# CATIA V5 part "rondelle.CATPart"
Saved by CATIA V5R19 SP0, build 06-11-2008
Part number: rondelle
Bounding box of the stored display mesh (mm): x 0 to 2.876, y -10 to 10, z -9.511 to 9.511
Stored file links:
  I:\mediator\rondelle.CATPart
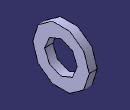
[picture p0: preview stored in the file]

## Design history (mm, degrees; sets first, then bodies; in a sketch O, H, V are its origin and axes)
Body1 (main body)
  Sketch1 on yz-plane, origin (0, 0, 0), H (0, 1, 0), V (0, 0, 1)
    circle A1 centre (0, 0) radius 5.75
    circle A2 centre (0, 0) radius 10
    radius A1 = 5.75
    radius A2 = 10
  Pad1: profile Sketch1, direction (1, 0, 0), length 2.876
